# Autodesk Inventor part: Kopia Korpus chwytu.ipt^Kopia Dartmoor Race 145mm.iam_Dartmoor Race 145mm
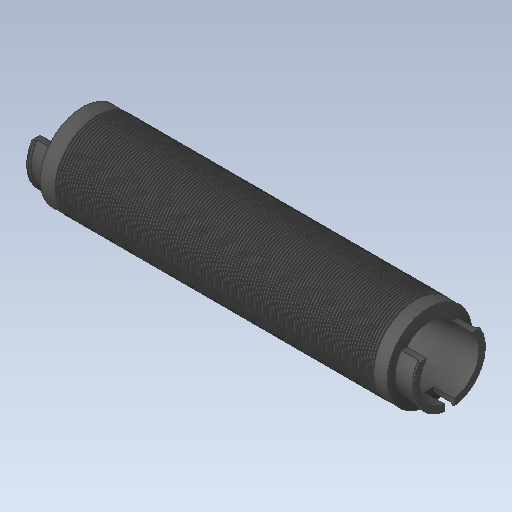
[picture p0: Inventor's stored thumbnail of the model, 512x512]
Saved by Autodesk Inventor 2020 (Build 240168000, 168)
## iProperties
Created: 2017-10
Part Number: Kopia Korpus chwytu.ipt^Kopia Dartmoor Race 145mm.iam_Dartmoor Race 145mm
Material: Ogólny
Document SubType Name: Modeling
Designer: Tomasz
Density: 1 g/cm^3
Appearance: Domyślna
Sending System: SolidWorks 2017
Last Author: Tomasz
Last Saved: 2017-10-01
Author: Tomasz
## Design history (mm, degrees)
feature "Korpus chwytu.ipt"
node "Bryła1"
